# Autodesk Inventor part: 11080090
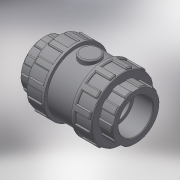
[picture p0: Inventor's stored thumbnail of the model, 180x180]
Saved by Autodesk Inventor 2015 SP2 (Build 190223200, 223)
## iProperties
Created: 2017-11
Part Number: 11080090
Material: Generic
Description: PLASSON CHECK VALVE CEM 90 PTFE COATED SPRING + EPDM O-RING
Document SubType Name: Modeling
Designer: KIM
Density: 1 g/cm^3
Appearance: Default
Author: KIM
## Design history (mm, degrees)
derived "110800 - 110600 110900-110000.ipt"
feature "Solid1::110800 - 110600 110900-110000.ipt"
tag "TaggingFeature1"
body "Solid1"
other parameters: "d2" = 165, "d3" = 51, "d4" = 72, "d5" = 35.7, "d7" = 126, "d8" = 148.5, "d13" = 2.7, "d23" = 51, "d24" = 158.4, "d25" = 1.8, "d26" = 2.7, "d27" = 24.75, "d28" = 12.375, "d29" = 38.25, "d30" = 0, "d35" = 2.7, "d39" = 82.5, "d45" = 360 deg, "d47" = 1.8, "d50" = 82.5, "d51" = 49.5, "d53" = 0, "d54" = 3.3, "d55" = 18, "d56" = 9, "d57" = 35.7, "d58" = 0, "d59" = 2.7, "d61" = 360 deg, "l_" = 51, "K_" = 165
